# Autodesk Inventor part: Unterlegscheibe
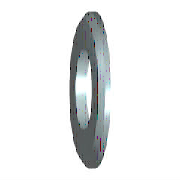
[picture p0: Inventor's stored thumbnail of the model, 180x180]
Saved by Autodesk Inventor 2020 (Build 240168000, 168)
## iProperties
Created: 2008-02
Part Number: Unterlegscheibe
Material: Stahl, weich, unlegiert
Document SubType Name: Modeling
Standard: DIN 125-1
Designer: Administrator
Standards Organization: DIN
Language: de-DE
Size Designation: B 5,3
Categories: <MemberInstance><Categories><Category DisplayName="Verbindungselemente" InternalName="e4da775c-781d-43d5-af7c-5136215cf5a6" Mnemonic="FSTN"><Category DisplayNam
Density: 7.86 g/cm^3
Mass: 0.436329 g
Surface Area: 1.5634 cm^2
Volume: 0.0555126 cm^3
Appearance: Stahl
User Status: A
IsCustomPart: 0
Author: Administrator
Revision Number: C
Title: Unterlegscheibe
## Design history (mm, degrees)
workaxis "Work Axis1"
workplane "Work Plane1"
node "Volumenkörper1"
sketch "Skizze"
  geometry: C1 r 5 at (0, 0); C2 r 2.65 at (0, 0); 1 further point
  constraints: 2 centre point, 2 coincident
  dimensions: "d0" = 5.3 diameter of C2 (= SD1); "d1" = 10 diameter of C1 (= SD2)
extrude "Körper" new body sketch "Skizze" distance "d2" = 1 (= SD); taper "d3" = 0 deg
node "Volumenkörpern"
node "Oberflächenkörpern"
chamfer "Fase" distance "d4" = 0.25 (= PHH); stored, may be unused: angle "d5" = 45 deg, second distance "d8" = 0.25 (= PHH)
other parameters: "SD1" = 5.3 [user parameter; used in 1 equation term], "SD2" = 10 [user parameter; used in 1 equation term], "SD" = 1 [user parameter; used in 1 equation term], "PHH" = 0.25 [user parameter; used in 2 equation terms], "FAWI" = 45 deg [user parameter], "d6" = 0, "d7" = 0, "d9" = 0, "d10" = 0, "NND" = 5 [user parameter]
